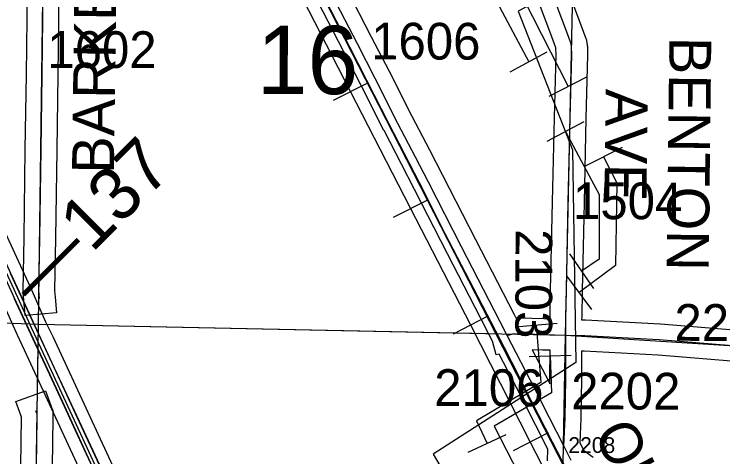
# Model space of a CAD drawing. Extents: x -157.2 to -99.3, y 12.2 to 46.2.
# Drawn here: x -144.882 to -143.532, y 25.924 to 26.767 of the extents above; entities that cross this region are included whole.
import ezdxf

# ---------------------------------------------------------------- set-up
doc = ezdxf.new("R2010")
doc.units = 0
for name, color, linetype in [('tdCoDivCarto', 7, 'Continuous'), ('tdCoInt', 7, 'Continuous'), ('tdCoIntCL', 7, 'Continuous'), ('tdCoIntRte', 7, 'Continuous'), ('tdCoPipe', 7, 'Continuous'), ('tdCoPipe1', 7, 'Continuous'), ('tdCoPipe2', 7, 'Continuous'), ('tdCoRRCL', 7, 'Continuous'), ('tdCoSecRdNmbr', 7, 'Continuous'), ('tdCoSecRdTxt', 7, 'Continuous'), ('tdCoSecRteBand', 7, 'Continuous'), ('tdCoSecRteCL', 7, 'Continuous'), ('tdCoSectLine', 7, 'Continuous'), ('tdCoSectLinePart', 7, 'Continuous'), ('tdCoSectNmbr', 7, 'Continuous'), ('tdCoSurfAsphalt', 7, 'Continuous'), ('tdCoSurfConc', 7, 'Continuous'), ('tdCoSurfGravel', 7, 'Continuous'), ('tdStHwyIntRefPost1', 7, 'Continuous')]:
    doc.layers.add(name, color=color, linetype=linetype)

msp = doc.modelspace()

# ---------------------------------------------------------------- linework, layer by layer
at = {"layer": 'tdCoDivCarto'}
for points in [[(-144.5268, 25.4922), (-144.5446, 25.5301), (-144.5853, 25.6187), (-144.6358, 25.7269), (-144.6935, 25.8534), (-144.7532, 25.9814), (-144.8097, 26.1025), (-144.8676, 26.2283), (-144.8886, 26.2729), (-144.9256, 26.3538), (-144.9544, 26.4157), (-144.9843, 26.4798), (-145.0062, 26.5284), (-145.0447, 26.61), (-145.0585, 26.6401), (-145.0814, 26.6865), (-145.1024, 26.7262), (-145.1682, 26.8443), (-145.2385, 26.9688), (-145.2565, 27.0007), (-145.3095, 27.0963), (-145.3835, 27.2263), (-145.4553, 27.3538), (-145.5303, 27.487)], [(-144.5268, 25.4922), (-144.5446, 25.5301), (-144.5853, 25.6187), (-144.6358, 25.7269), (-144.6935, 25.8534), (-144.7532, 25.9814), (-144.8097, 26.1025), (-144.8676, 26.2283), (-144.8886, 26.2729), (-144.9256, 26.3538), (-144.9544, 26.4157), (-144.9843, 26.4798), (-145.0062, 26.5284), (-145.0447, 26.61), (-145.0585, 26.6401), (-145.0814, 26.6865), (-145.1024, 26.7262), (-145.1682, 26.8443), (-145.2385, 26.9688), (-145.2565, 27.0007), (-145.3095, 27.0963), (-145.3835, 27.2263), (-145.4553, 27.3538), (-145.5303, 27.487)], [(-144.9352, 26.3412), (-144.8822, 26.2267), (-144.8422, 26.1402), (-144.8225, 26.0987), (-144.7902, 26.0287), (-144.7653, 25.9744), (-144.7155, 25.8669), (-144.6694, 25.7671), (-144.6171, 25.6534), (-144.5951, 25.6074), (-144.5835, 25.5831), (-144.5739, 25.5631), (-144.5726, 25.5601)], [(-144.9352, 26.3412), (-144.8822, 26.2267), (-144.8422, 26.1402), (-144.8225, 26.0987), (-144.7902, 26.0287), (-144.7653, 25.9744), (-144.7155, 25.8669), (-144.6694, 25.7671), (-144.6171, 25.6534), (-144.5951, 25.6074), (-144.5835, 25.5831), (-144.5739, 25.5631), (-144.5726, 25.5601)]]:
    msp.add_lwpolyline(points, dxfattribs=at)
at = {"layer": 'tdCoInt'}
for points in [[(-144.2883, 25.2066), (-144.3658, 25.3), (-144.3919, 25.3324), (-144.4398, 25.3921), (-144.4543, 25.4114), (-144.4745, 25.4424), (-144.4946, 25.4783), (-144.508, 25.5047), (-144.5221, 25.5353), (-144.5684, 25.6351), (-144.8081, 26.1525), (-144.8216, 26.1806), (-144.8478, 26.2398), (-145.0204, 26.6132), (-145.0466, 26.6685), (-145.0811, 26.7352), (-145.0939, 26.7581), (-145.2516, 27.0373), (-145.349, 27.2141), (-145.4057, 27.3125), (-145.5032, 27.4853)], [(-144.3677, 25.2083), (-144.4123, 25.262), (-144.4387, 25.2948), (-144.4871, 25.3552), (-144.5035, 25.3769), (-144.5259, 25.4114), (-144.5475, 25.4501), (-144.562, 25.4785), (-144.5766, 25.5101), (-144.6229, 25.6099), (-144.8624, 26.1269), (-144.8761, 26.1556), (-144.9025, 26.2151), (-145.0747, 26.5877), (-145.1004, 26.6418), (-145.134, 26.7069), (-145.1462, 26.7289), (-145.304, 27.0081), (-145.4013, 27.1846), (-145.4579, 27.2828), (-145.5556, 27.456)]]:
    msp.add_lwpolyline(points, dxfattribs=at)
at = {"layer": 'tdCoIntCL'}
msp.add_lwpolyline([(-144.4633, 25.3719), (-144.4794, 25.3946), (-144.4899, 25.4097), (-144.4997, 25.4255), (-144.5094, 25.4426), (-144.5335, 25.4892), (-144.5393, 25.5015), (-144.5494, 25.5227), (-144.5679, 25.5624), (-144.8353, 26.1397), (-144.8488, 26.1681), (-144.8751, 26.2275), (-145.0475, 26.6004), (-145.0735, 26.6552), (-145.1076, 26.721), (-145.12, 26.7435), (-145.2778, 27.0227), (-145.3751, 27.1994), (-145.4318, 27.2976), (-145.5294, 27.4706)], dxfattribs=at)
at = {"layer": 'tdCoIntRte'}
for points in [[(-144.6939, 25.8534), (-144.7536, 25.9814), (-144.81, 26.1025), (-144.868, 26.2283), (-144.889, 26.2729)], [(-144.6939, 25.8534), (-144.7536, 25.9814), (-144.81, 26.1025), (-144.868, 26.2283), (-144.889, 26.2729)], [(-144.8826, 26.2267), (-144.8426, 26.1402), (-144.8229, 26.0987), (-144.7906, 26.0287), (-144.7657, 25.9744), (-144.7159, 25.8669)], [(-144.8826, 26.2267), (-144.8426, 26.1402), (-144.8229, 26.0987), (-144.7906, 26.0287), (-144.7657, 25.9744), (-144.7159, 25.8669)]]:
    msp.add_lwpolyline(points, dxfattribs=at)
at = {"layer": 'tdCoPipe'}
msp.add_lwpolyline([(-144.5317, 38.1832), (-143.5928, 36.8918), (-143.6099, 34.8602), (-143.4402, 34.5415), (-143.5694, 34.3304), (-143.5634, 33.7239), (-143.4667, 33.4993), (-143.5656, 33.4168), (-143.4755, 33.1706), (-143.455, 32.2186), (-143.5122, 31.3968), (-143.6938, 30.9939), (-143.6811, 29.9265), (-143.7347, 27.6406), (-143.7362, 26.8708), (-143.9217, 26.7732), (-143.8183, 26.5085), (-143.8116, 26.1034), (-144.0839, 25.9289), (-143.0557, 24.1836)], dxfattribs=at)
at = {"layer": 'tdCoPipe1'}
for p, q in [((-143.8624, 26.6113), (-143.7909, 26.6476)), ((-143.7946, 26.4776), (-143.7231, 26.5138)), ((-143.8295, 26.269), (-143.7819, 26.2045)), ((-143.901, 26.1148), (-143.8209, 26.1178))]:
    msp.add_line(p, q, dxfattribs=at)
for points in [[(-143.9624, 26.897), (-143.8267, 26.6295)], [(-143.7588, 26.4957), (-143.7337, 26.446), (-143.7361, 26.2882), (-143.8057, 26.2368)], [(-143.8609, 26.1163), (-143.8583, 26.0456), (-143.9677, 25.9822), (-143.9207, 25.8907)]]:
    msp.add_lwpolyline(points, dxfattribs=at)
at = {"layer": 'tdCoPipe2'}
for p, q in [((-143.937, 26.6576), (-143.8662, 26.6952)), ((-143.8666, 26.5251), (-143.7958, 26.5627)), ((-143.8237, 26.3104), (-143.7784, 26.2443)), ((-143.9274, 26.1716), (-143.8475, 26.1783)), ((-144.0171, 25.9324), (-143.9446, 25.9666))]:
    msp.add_line(p, q, dxfattribs=at)
for points in [[(-144.0327, 26.9407), (-144.038, 26.9331), (-143.9016, 26.6764)], [(-143.8312, 26.5439), (-143.7675, 26.4239), (-143.7675, 26.3004), (-143.801, 26.2774)], [(-143.8875, 26.1749), (-143.8782, 26.0656), (-144.0009, 25.9922), (-143.9808, 25.9495)]]:
    msp.add_lwpolyline(points, dxfattribs=at)
at = {"layer": 'tdCoRRCL'}
for p, q in [((-144.2074, 26.6366), (-144.2744, 26.6029)), ((-144.0931, 26.4138), (-144.1601, 26.38)), ((-143.9792, 26.192), (-144.0457, 26.1575)), ((-143.8644, 25.9695), (-143.931, 25.9351))]:
    msp.add_line(p, q, dxfattribs=at)
for points in [[(-142.7262, 23.739), (-143.1704, 24.6), (-143.4255, 25.1074), (-144.37, 26.9512), (-144.9761, 28.127), (-145.218, 28.6071), (-145.4618, 29.0746), (-145.6726, 29.4889)], [(-142.984, 24.1736), (-143.0984, 24.3958), (-143.2126, 24.6181), (-143.3271, 24.8407), (-143.4403, 25.0634), (-143.5554, 25.2851), (-143.6701, 25.5081), (-143.7843, 25.7301), (-143.8986, 25.9522), (-144.0122, 26.1747), (-144.1269, 26.3975), (-144.241, 26.6197), (-144.3551, 26.8418), (-144.4697, 27.0637), (-144.5841, 27.286), (-144.6989, 27.509), (-144.8132, 27.7309), (-144.9272, 27.9528), (-145.0424, 28.1754), (-145.1566, 28.3975), (-145.2703, 28.62), (-145.3849, 28.8426), (-145.4992, 29.0643), (-145.6132, 29.2868)], [(-143.8195, 25.8805), (-143.8562, 25.9518), (-143.8694, 25.9775), (-143.8965, 26.0301), (-143.9195, 26.0768), (-143.9475, 26.1314), (-144.0142, 26.26), (-144.0606, 26.3485), (-144.1096, 26.4458), (-144.1685, 26.559), (-144.2099, 26.6412), (-144.2589, 26.7369), (-144.3082, 26.8322), (-144.4037, 27.0168), (-144.5477, 27.2967), (-144.6529, 27.5006)]]:
    msp.add_lwpolyline(points, dxfattribs=at)
at = {"layer": 'tdCoSecRteBand'}
for points in [[(-143.8528, 26.8822), (-143.8015, 26.7451), (-143.8015, 26.745), (-143.8015, 26.745), (-143.7926, 26.7211), (-143.7916, 26.7184), (-143.7912, 26.7156), (-143.7902, 26.7096), (-143.7899, 26.7077), (-143.7898, 26.7058), (-143.7893, 26.6917), (-143.7893, 26.6908), (-143.7893, 26.6898), (-143.7927, 26.5683), (-143.7962, 26.4084), (-143.7962, 26.4084), (-143.7962, 26.4084), (-143.7999, 26.2398), (-143.8006, 26.1905), (-143.8007, 26.1858), (-143.8007, 26.1851), (-143.7939, 26.1849), (-143.7936, 26.1849), (-143.7932, 26.1849), (-143.6512, 26.1775), (-143.6507, 26.1775), (-143.6503, 26.1774), (-143.5108, 26.1661)], [(-143.8606, 26.1868), (-143.8606, 26.1909), (-143.8606, 26.1911), (-143.8606, 26.1912), (-143.8599, 26.2408), (-143.8599, 26.2409), (-143.8599, 26.241), (-143.8562, 26.4097), (-143.8527, 26.5697), (-143.8527, 26.5698), (-143.8527, 26.5699), (-143.8493, 26.6906), (-143.8497, 26.7017), (-143.8499, 26.7029), (-143.8578, 26.7241), (-143.9085, 26.8596)], [(-144.7969, 26.812), (-144.7989, 26.6517), (-144.7989, 26.6517), (-144.7989, 26.6516), (-144.8011, 26.5086), (-144.8033, 26.3407), (-144.8033, 26.3406), (-144.8033, 26.3405), (-144.8053, 26.2408), (-144.8042, 26.2283), (-144.8016, 26.1984), (-144.8613, 26.1932), (-144.864, 26.2231), (-144.8652, 26.2371), (-144.8653, 26.2387), (-144.8653, 26.2403), (-144.8633, 26.3416), (-144.8611, 26.5094), (-144.8611, 26.5095), (-144.8611, 26.5095), (-144.8589, 26.6525), (-144.8569, 26.8127)], [(-144.2494, 26.8177), (-144.2016, 26.7242), (-144.1678, 26.6587), (-144.1678, 26.6586), (-144.1677, 26.6585), (-144.1241, 26.5728), (-144.0909, 26.5088), (-144.0909, 26.5087), (-144.0908, 26.5087), (-144.0662, 26.4606), (-144.0028, 26.3379), (-144.0028, 26.3378), (-144.0028, 26.3378), (-143.9293, 26.1948), (-143.926, 26.1884), (-143.922, 26.1888), (-143.9202, 26.1889), (-143.9184, 26.1888), (-143.8729, 26.1871), (-143.8606, 26.1868)], [(-143.8659, 25.9159), (-143.8649, 25.938), (-143.875, 25.9577), (-143.8888, 25.9847), (-143.8888, 25.9847), (-143.8888, 25.9847), (-143.9168, 26.0399), (-143.958, 26.1195), (-143.9634, 26.118), (-143.9706, 26.1439), (-143.9826, 26.1673), (-143.9827, 26.1673), (-143.9827, 26.1673), (-143.9829, 26.1678), (-144.0561, 26.3104), (-144.1195, 26.4331), (-144.1195, 26.4332), (-144.1195, 26.4332), (-144.1442, 26.4812), (-144.1774, 26.5453), (-144.1775, 26.5454), (-144.1775, 26.5455), (-144.2212, 26.6313), (-144.2549, 26.6968), (-144.2549, 26.6968), (-144.2549, 26.6969), (-144.3027, 26.7902)], [(-143.8613, 26.063), (-143.8611, 26.073), (-143.8609, 26.1268), (-143.8616, 26.1268), (-143.8748, 26.1272), (-143.8749, 26.1272), (-143.8751, 26.1272), (-143.8948, 26.1279), (-143.8635, 26.0673), (-143.8634, 26.0673), (-143.8634, 26.0672), (-143.8613, 26.063)], [(-143.5156, 26.1063), (-143.6547, 26.1176), (-143.796, 26.1249), (-143.8009, 26.1251), (-143.8011, 26.0725), (-143.8011, 26.0724), (-143.8011, 26.0722), (-143.8024, 25.9974), (-143.8024, 25.9971), (-143.8024, 25.9967), (-143.8043, 25.9512), (-143.797, 25.9368), (-143.7785, 25.9231)], [(-144.8703, 25.8596), (-144.8683, 25.9985), (-144.8683, 25.9992), (-144.869, 26.0011), (-144.8792, 26.0293), (-144.8228, 26.0498), (-144.8126, 26.0216), (-144.812, 26.02), (-144.8111, 26.018), (-144.8083, 26.012), (-144.8083, 26.0054), (-144.8083, 25.9982), (-144.8083, 25.998), (-144.8083, 25.9978), (-144.8103, 25.8587)]]:
    msp.add_lwpolyline(points, dxfattribs=at)
at = {"layer": 'tdCoSecRteCL'}
msp.add_line((-143.8205, 25.917), (-143.8346, 25.9446), dxfattribs=at)
for points in [[(-144.8341, 26.2257), (-144.8353, 26.2398), (-144.8333, 26.3411), (-144.8311, 26.509), (-144.8289, 26.6521), (-144.8269, 26.8124), (-144.8247, 26.9852), (-144.8227, 27.1517), (-144.8185, 27.3073), (-144.8143, 27.4819), (-144.8097, 27.6481), (-144.8052, 27.6781)], [(-143.9425, 26.1549), (-143.956, 26.1811), (-144.0295, 26.3241), (-144.0929, 26.4469), (-144.1175, 26.495), (-144.1508, 26.5591), (-144.1945, 26.6449), (-144.2282, 26.7105), (-144.2761, 26.804), (-144.3237, 26.8955), (-144.3639, 26.9744), (-144.4184, 27.0797), (-144.4502, 27.1418), (-144.4607, 27.1624)], [(-143.8308, 26.1559), (-143.8306, 26.1908), (-143.8299, 26.2404), (-143.8262, 26.409), (-143.8227, 26.5691), (-143.8193, 26.6907), (-143.8198, 26.7047), (-143.8208, 26.7106), (-143.8296, 26.7346), (-143.8809, 26.8717), (-143.893, 26.8956), (-143.9088, 26.9235), (-143.9591, 27.0083), (-144.004, 27.0835), (-144.0252, 27.1175), (-144.0336, 27.1289), (-144.0472, 27.142), (-144.0509, 27.1466), (-144.052, 27.1503)], [(-143.9425, 26.1549), (-143.9316, 26.1579), (-143.9196, 26.1589), (-143.8739, 26.1571), (-143.8308, 26.1559)], [(-143.8346, 25.9446), (-143.862, 25.9983), (-143.8901, 26.0536), (-143.9425, 26.1549)], [(-143.8346, 25.9446), (-143.8324, 25.9979), (-143.8311, 26.0727), (-143.8308, 26.1559)], [(-143.8308, 26.1559), (-143.7948, 26.1549), (-143.6527, 26.1475), (-143.5131, 26.1362), (-143.3768, 26.1263), (-143.3269, 26.1241)], [(-144.8504, 25.1741), (-144.8501, 25.1872), (-144.8472, 25.3376), (-144.8455, 25.4814), (-144.8452, 25.5107), (-144.8427, 25.6897), (-144.8403, 25.8592), (-144.8383, 25.9982), (-144.8383, 26.0054), (-144.8398, 26.0086), (-144.8408, 26.0113)]]:
    msp.add_lwpolyline(points, dxfattribs=at)
at = {"layer": 'tdCoSectLine'}
for points in [[(-144.836, 26.1765), (-144.8224, 27.1764)], [(-143.8312, 26.1559), (-143.8108, 27.142)], [(-145.8467, 26.2152), (-144.836, 26.1765)], [(-144.8508, 25.1741), (-144.836, 26.1765)], [(-144.836, 26.1765), (-143.8312, 26.1559)], [(-143.8497, 25.1417), (-143.8312, 26.1559)], [(-143.8312, 26.1559), (-143.3272, 26.1241), (-142.8275, 26.1035)]]:
    msp.add_lwpolyline(points, dxfattribs=at)
at = {"layer": 'tdCoSectLinePart'}
for points in [[(-145.8165, 26.2141), (-144.836, 26.1765)], [(-144.836, 26.1765), (-144.8358, 26.1955)], [(-144.838, 26.0451), (-144.836, 26.1765)], [(-144.836, 26.1765), (-143.979, 26.159)]]:
    msp.add_lwpolyline(points, dxfattribs=at)
at = {"layer": 'tdCoSurfAsphalt'}
msp.add_lwpolyline([(-143.8205, 25.917), (-143.8346, 25.9446), (-143.862, 25.9983), (-143.8901, 26.0536), (-143.9425, 26.1549), (-143.956, 26.1811), (-144.0295, 26.3241), (-144.0929, 26.4469), (-144.1175, 26.495), (-144.1508, 26.5591), (-144.1945, 26.6449), (-144.2282, 26.7105), (-144.2761, 26.804), (-144.3237, 26.8955), (-144.3639, 26.9744), (-144.4184, 27.0797), (-144.4502, 27.1418), (-144.4607, 27.1624), (-144.485, 27.2094), (-144.5326, 27.3024), (-144.5774, 27.3894), (-144.6164, 27.4649)], dxfattribs=at)
at = {"layer": 'tdCoSurfConc'}
msp.add_lwpolyline([(-143.9425, 26.1549), (-143.9316, 26.1579), (-143.9196, 26.1589), (-143.8739, 26.1571), (-143.8308, 26.1559), (-143.7948, 26.1549), (-143.6527, 26.1475), (-143.5131, 26.1362), (-143.3768, 26.1263), (-143.3269, 26.1241), (-143.1901, 26.1179), (-143.0172, 26.111), (-142.8439, 26.1041), (-142.6485, 26.0965)], dxfattribs=at)
at = {"layer": 'tdCoSurfGravel'}
for points in [[(-144.8341, 26.2257), (-144.8353, 26.2398), (-144.8333, 26.3411), (-144.8311, 26.509), (-144.8289, 26.6521), (-144.8269, 26.8124), (-144.8247, 26.9852), (-144.8227, 27.1517), (-144.8185, 27.3073), (-144.8143, 27.4819), (-144.8097, 27.6481), (-144.8052, 27.6781)], [(-143.8346, 25.9446), (-143.8324, 25.9979), (-143.8311, 26.0727), (-143.8308, 26.1559), (-143.8306, 26.1908), (-143.8299, 26.2404), (-143.8262, 26.409), (-143.8227, 26.5691), (-143.8193, 26.6907), (-143.8198, 26.7047), (-143.8208, 26.7106), (-143.8296, 26.7346), (-143.8809, 26.8717), (-143.893, 26.8956), (-143.9088, 26.9235), (-143.9591, 27.0083), (-144.004, 27.0835), (-144.0252, 27.1175), (-144.0336, 27.1289), (-144.0472, 27.142), (-144.0509, 27.1466), (-144.052, 27.1503)], [(-144.8504, 25.1741), (-144.8501, 25.1872), (-144.8472, 25.3376), (-144.8455, 25.4814), (-144.8452, 25.5107), (-144.8427, 25.6897), (-144.8403, 25.8592), (-144.8383, 25.9982), (-144.8383, 26.0054), (-144.8398, 26.0086), (-144.8408, 26.0113)]]:
    msp.add_lwpolyline(points, dxfattribs=at)

# ---------------------------------------------------------------- texts
at = {"layer": 'tdCoSecRdNmbr'}
for s, height, rotation, p in [('1606', 0.07, 359.8899, (-144.2019, 26.681)), ('1602', 0.07, 359.8895, (-144.8191, 26.665)), ('1504', 0.07, 359.8902, (-143.8172, 26.3768)), ('2103', 0.07, 269.8908, (-143.9267, 26.3578)), ('2201', 0.07, 359.8904, (-143.6239, 26.1449)), ('2106', 0.07, 359.89, (-144.0818, 26.0208)), ('2202', 0.07, 359.8902, (-143.8208, 26.0142)), ('2208', 0.03, 359.8945, (-143.826, 25.9313))]:
    msp.add_text(s, height=height, rotation=rotation, dxfattribs=at).set_placement(p)
at = {"layer": 'tdCoSecRdTxt'}
for s, rotation, p in [('BARKER AVE', 89.2471, (-144.6921, 26.4629)), ('BENTON', 269.3291, (-143.6335, 26.7244)), ('AVE', 269.3291, (-143.7547, 26.625)), ('OLD HWY 75', 297.3738, (-143.7797, 25.9682))]:
    msp.add_text(s, height=0.08, rotation=rotation, dxfattribs=at).set_placement(p)
at = {"layer": 'tdCoSectNmbr'}
msp.add_text('16', height=0.13, rotation=359.8897, dxfattribs=at).set_placement((-144.4199, 26.6152))
at = {"layer": 'tdStHwyIntRefPost1'}
msp.add_text('‒‒137', height=0.1, rotation=45, dxfattribs=at).set_placement((-144.839, 26.2064))

doc.saveas('drawing.dxf')
